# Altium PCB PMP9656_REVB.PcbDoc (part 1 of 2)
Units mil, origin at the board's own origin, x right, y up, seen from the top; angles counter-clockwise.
Board outline 5000 x 2000 mil, 4 copper layers (Top Layer, MidLayer1, MidLayer2, Bottom Layer), stack 60.2 mil thick; 89 components, 41 nets, 276 pads, 85 vias.
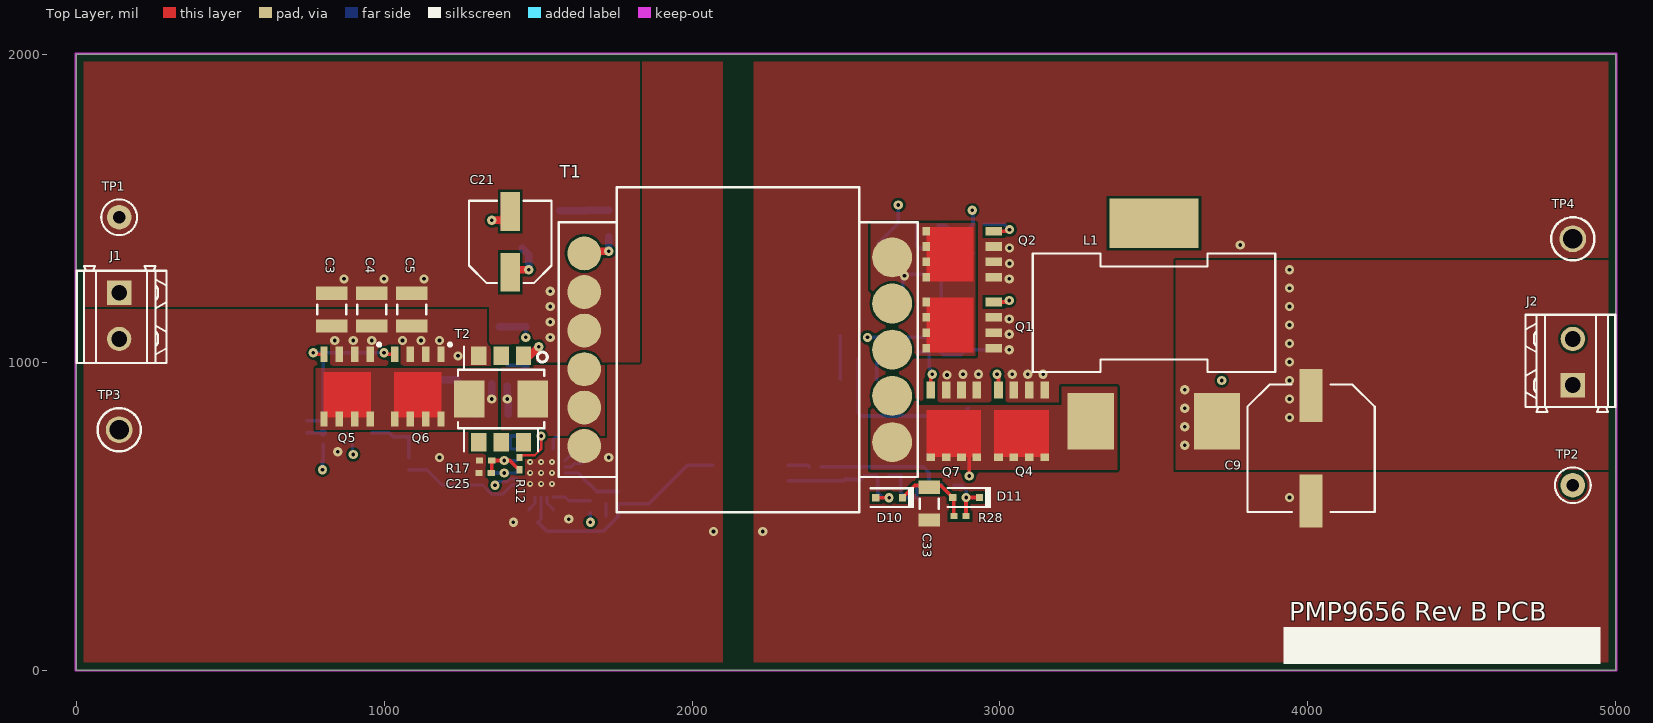
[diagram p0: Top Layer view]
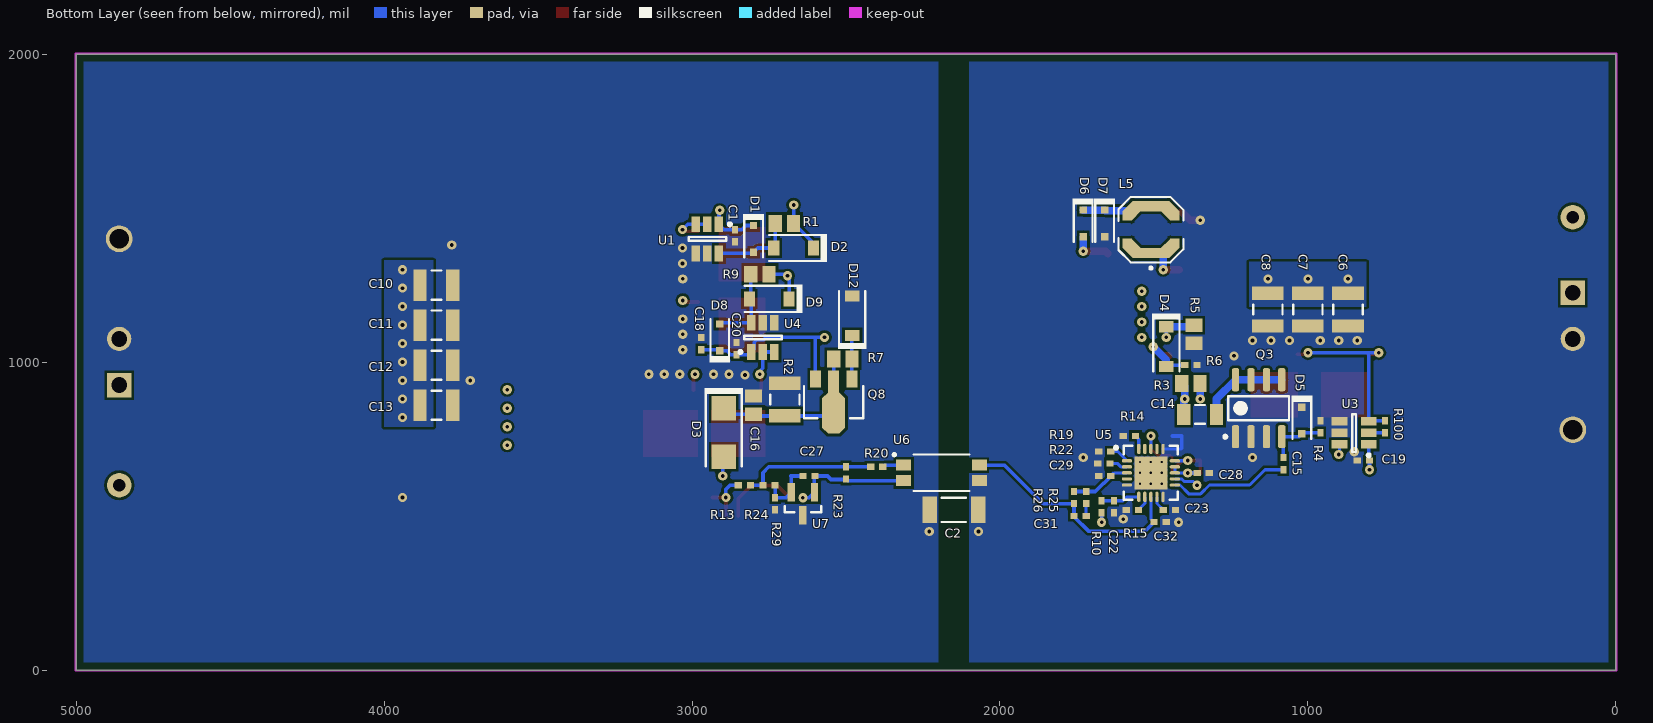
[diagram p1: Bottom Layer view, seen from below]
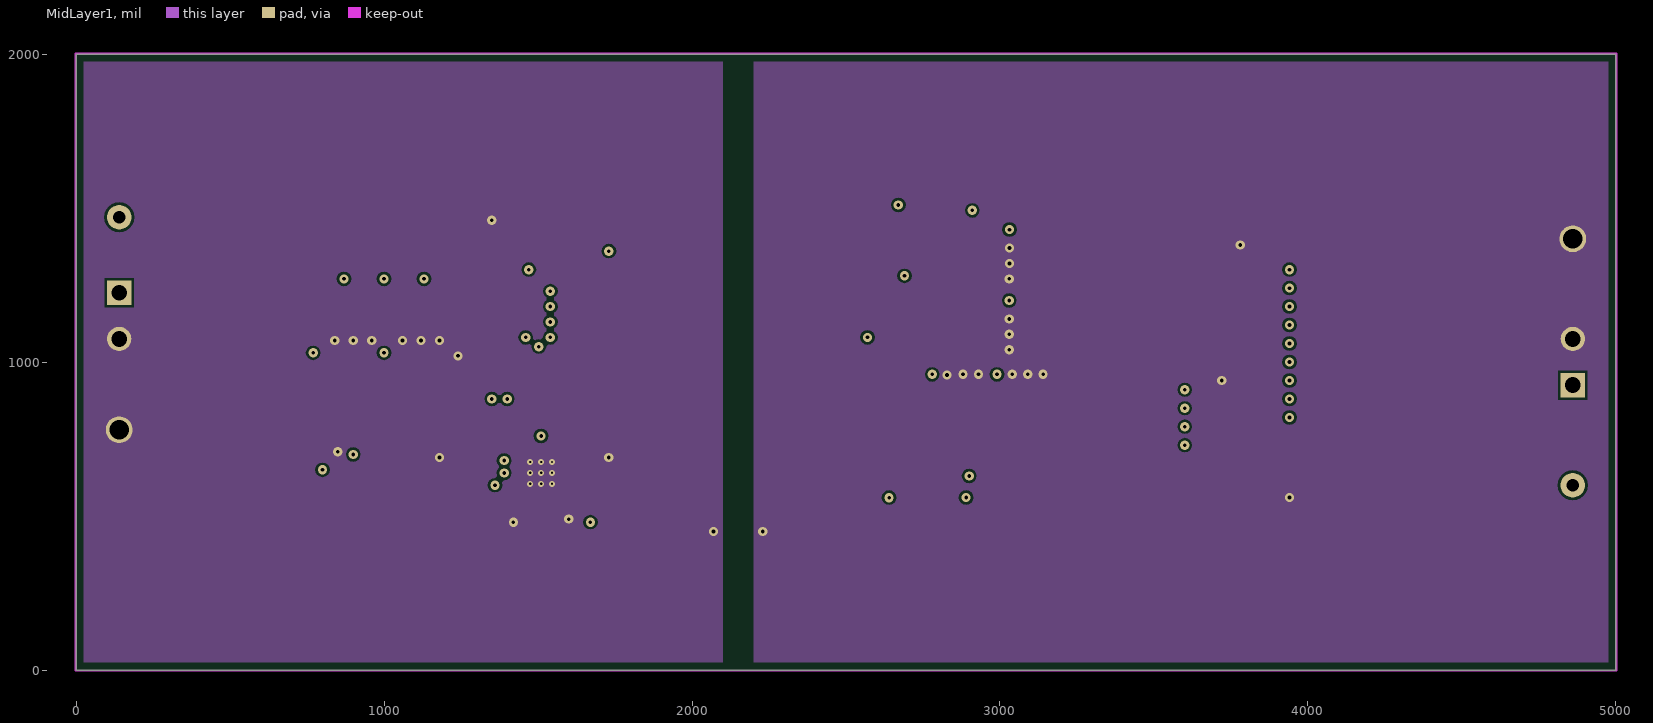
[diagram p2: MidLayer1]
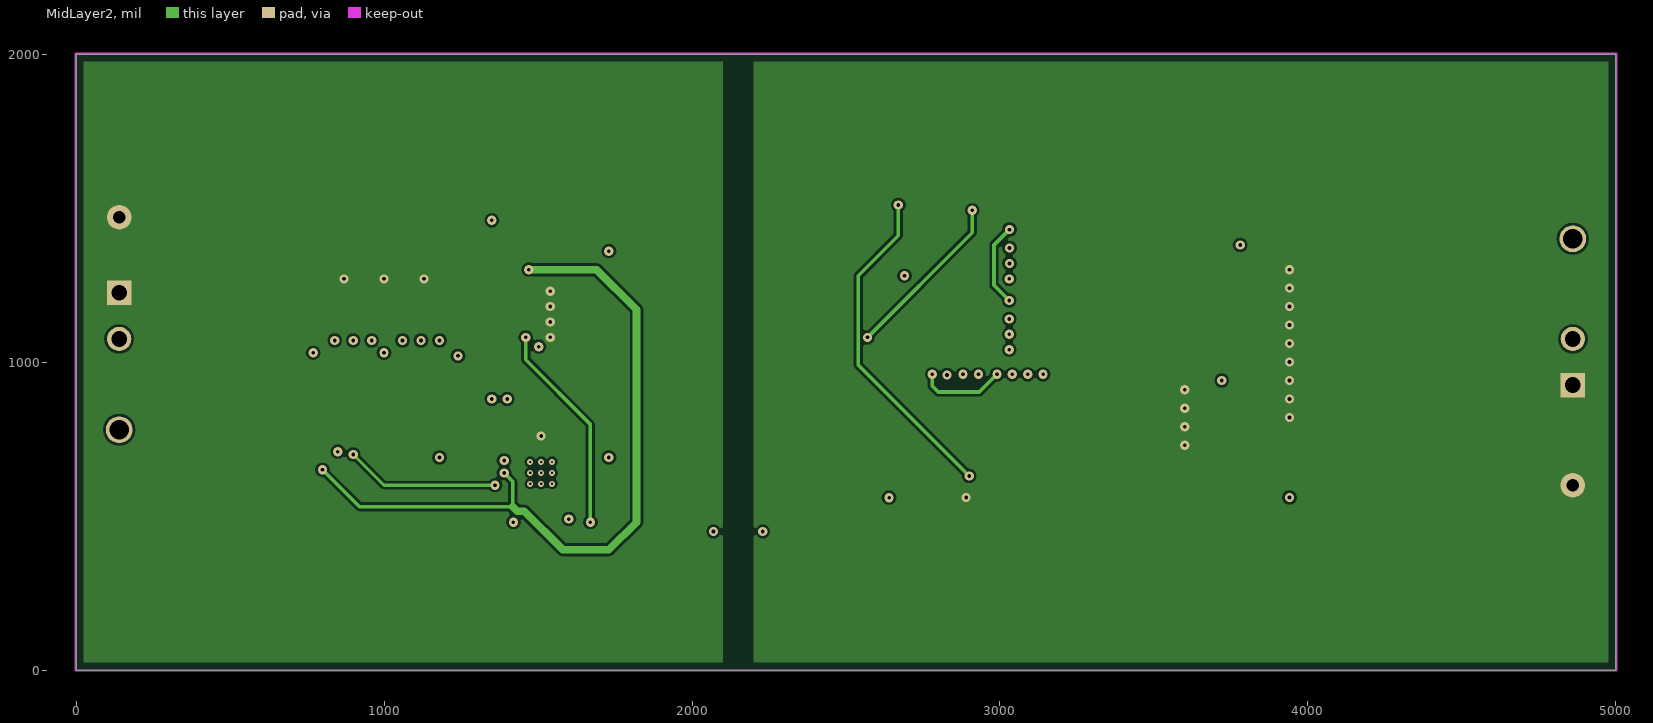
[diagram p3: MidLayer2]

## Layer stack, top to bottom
Top Solder: solder mask 0.4, Solder Resist, Dk 3.5
Top Layer: signal copper 1.4
Dielectric1: core 18.2, FR-4, Dk 4.8
MidLayer1: signal copper 1.4
Dielectric2: prepreg 18.2, FR-4, Dk 4.8
MidLayer2: signal copper 1.4
Dielectric3: core 18.2, FR-4, Dk 4.8
Bottom Layer: signal copper 1.4
Bottom Solder: solder mask 0.4, Solder Resist, Dk 3.5

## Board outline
0,0 5000,0 5000,2000 0,2000

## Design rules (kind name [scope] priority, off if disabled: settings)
AcuteAngle [All] p1: minimum=1.50000000000000E+0001 checktracksonly=TRUE
AssemblyTestPointUsage [All] p1: valid=2
Clearance Clearance_BoardEdge_MountingHoles [OnCopper and InComponentClass('Mounting Holes') vs IsKeepOut] p1: gap=25 ignorepadtopadclearanceinfootprint=FALSE except(0: Arc-Hole Track-Hole SMDPad-Hole THPad-Hole Via-Hole Fill-Hole Poly-Hole Region-Hole Text-Hole)
Clearance Clearance_BoardEdge_Poly [OnCopper and InPoly vs IsKeepOut] p2: gap=25 ignorepadtopadclearanceinfootprint=FALSE except(0: Arc-Hole Track-Hole SMDPad-Hole THPad-Hole Via-Hole Fill-Hole Poly-Hole Region-Hole Text-Hole)
Clearance Clearance_BoardEdge [OnCopper and Not InComponentClass('Logo') and not InComponentClass('FiducialMark') and not InRegion(1000,500,4000,800) and Not IsKeepout vs IsKeepOut] p3: gap=25 ignorepadtopadclearanceinfootprint=FALSE except(0: Arc-Hole Track-Hole SMDPad-Hole THPad-Hole Via-Hole Fill-Hole Poly-Hole Region-Hole Text-Hole)
Clearance Clearance_Poly [InPolygon] p4: gap=8 ignorepadtopadclearanceinfootprint=FALSE except(0: Arc-Hole Track-Hole SMDPad-Hole THPad-Hole Via-Hole Fill-Hole Poly-Hole Region-Hole Text-Hole)
Clearance [All] p5: gap=8 ignorepadtopadclearanceinfootprint=FALSE except(0: Arc-Hole Track-Hole SMDPad-Hole THPad-Hole Via-Hole Fill-Hole Poly-Hole Region-Hole Text-Hole)
ComponentClearance ComponentClearance_Shunt [InComponentClass('Header') vs InComponentClass('Shunt')] p1: gap=0 collisioncheckmode=3 verticalgap=0 showdistances=FALSE
ComponentClearance ComponentClearance_Logo [InComponentClass('Logo')] p2: gap=15 collisioncheckmode=3 verticalgap=10 showdistances=FALSE
ComponentClearance ComponentClearance_ScrewToNut [(HasFootprint('NY PMS 440 0025 PH')) vs (HasFootprint('Keystone_1902C'))] p3: gap=5 collisioncheckmode=3 verticalgap=10 showdistances=FALSE
ComponentClearance ComponentClearance_MountingHoles [InComponentClass('Mounting Holes')] p4: gap=15 collisioncheckmode=3 verticalgap=100000 showdistances=FALSE
ComponentClearance ComponentClearance_SmallPassives [HasFootprint('0201*') or HasFootprint('0402*') or HasFootprint('0508') or HasFootprint('0603*') or HasFootprint('0612') or HasFootprint('0805*') or HasFootprint('0815*') or HasFootprint('0830*') or HasFootprint('1206*') or HasFootprint('1210*') or HasFootprint('1808*') or HasFootprint('1812*') or HasFootprint('1825*') or HasFootprint('2010*') or HasFootprint('2220*') or HasFootprint('2225*') or HasFootprint('2512*') or HasFootprint('2728*') or HasFootprint('3518*') vs HasFootprint('0201*') or HasFootprint('0402*') or HasFootprint('0508') or HasFootprint('0603*') or HasFootprint('0612') or HasFootprint('0805*') or HasFootprint('0815*') or HasFootprint('0830*') or HasFootprint('1206*') or HasFootprint('1210*') or HasFootprint('1808*') or HasFootprint('1812*') or HasFootprint('1825*') or HasFootprint('2010*') or HasFootprint('2220*') or HasFootprint('2225*') or HasFootprint('2512*') or HasFootprint('2728*') or HasFootprint('3518*')] p5: gap=15 collisioncheckmode=3 verticalgap=10 showdistances=FALSE
ComponentClearance ComponentClearance_THtoSMT [IsThruComponent vs IsSMTComponent] p6: gap=15 collisioncheckmode=3 verticalgap=30 showdistances=FALSE
ComponentClearance ComponentClearance_THtoTH [IsThruComponent vs IsThruComponent] p7: gap=15 collisioncheckmode=3 verticalgap=30 showdistances=FALSE
ComponentClearance [All] p8: gap=15 collisioncheckmode=3 verticalgap=10 showdistances=FALSE
DiffPairsRouting [All] p1: maxlimit=100 minlimit=10 mostfreqgap=10 toplayer_minwidth=15 toplayer_maxwidth=15 toplayer_prefwidth=15 midlayer1_minwidth=15 midlayer1_maxwidth=15 midlayer1_prefwidth=15 midlayer2_minwidth=15 midlayer2_maxwidth=15 midlayer2_prefwidth=15 bottomlayer_minwidth=15 bottomlayer_maxwidth=15 bottomlayer_prefwidth=15 maxuncoupledlength=1000
FabricationTestPointUsage TestPointUsage [All] p1: valid=2 allowmultiple=FALSE
FabricationTestpoint Testpoint [All] p1: side=3 testpointundercomponent=TRUE minsize=40 maxsize=100 preferedsize=60 minholesize=0 maxholesize=40 preferedholesize=32 testpointgrid=1 allowsidetop=TRUE allowsidebottom=TRUE usegrid=TRUE gridtolerance=0.01
FanoutControl Fanout_LCC [IsLCC] p1: bgadir=Out bgaviamode=Centered fanoutstyle=Auto fanoutdirection=Alternating viagrid=1 // Fanout_LCC (Default Rule)
FanoutControl Fanout_BGA [IsBGA] p2: bgadir=Out bgaviamode=Centered fanoutstyle=Auto fanoutdirection=Alternating viagrid=1 // Fanout_BGA (Default Rule)
FanoutControl Fanout_Default [All] p4: bgadir=Out bgaviamode=Centered fanoutstyle=Auto fanoutdirection=Alternating viagrid=1 // Fanout_Default (Default Rule)
FanoutControl Fanout_Small [(CompPinCount < 5)] p5: bgadir=Out bgaviamode=Centered fanoutstyle=Auto fanoutdirection=OutThenIn viagrid=1 // Fanout_Small (Default Rule)
HoleSize [All] p1: absolutevalues=TRUE maxlimit=251 minlimit=7.8 maxpercent=80.000 minpercent=20.000
MinimumAnnularRing MinimumAnnularRing_ThermalPadVias [IsVia and InAnyComponent] p1: minimumring=5.91
MinimumAnnularRing [All] p2: minimumring=9
MinimumSolderMaskSliver MinimumSolderMaskSliver_Logo [InComponentClass('Logo') vs InComponentClass('Logo')] p1: minsoldermaskwidth=0.7
MinimumSolderMaskSliver [All] p2: minsoldermaskwidth=0
PlaneConnect [All] p1: planeconnectstyle=Relief reliefexpansion=10 reliefentries=4 reliefconductorwidth=10 reliefairgap=10
PolygonConnect [All] p1: connectstyle=Direct reliefconductorwidth=10 reliefentries=4 polygonreliefangle="90 Angle" airgapwidth=10
RoutingVias ThermalPadVias [IsVia and InAnyComponent] p1: holewidth=7.87 width=19.68 viastyle="Through Hole" minholewidth=7.87 minwidth=19.68 maxholewidth=12.99 maxwidth=23.62
RoutingVias [All] p2: holewidth=16 width=34 viastyle="Through Hole" minholewidth=7.87 minwidth=26 maxholewidth=40 maxwidth=65
SMDToCorner [All] p1: distance=0
SilkToSilkClearance [All] p1: silktosilkclearance=0
SilkToSolderMaskClearance SilkscreenOverComponentPads [IsPad] p1: minsilkscreentomaskgap=0 clearancetoexposedcopper=TRUE
SolderMaskExpansion [All] p1: expansion=1.97
Width [All] p1: maxlimit=100 minlimit=6 preferedwidth=10 checkconnectedcopper=TRUE
16 further rules are at their usual default settings.

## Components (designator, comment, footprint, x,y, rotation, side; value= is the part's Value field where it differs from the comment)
C1 "C1005X7R1H104M" 0402L 2860,1410 r270 bottom value=0.1uF
C2 "STD" 1808_L 2150,520 r180 bottom value=1000pF
C3 "GRM32ER72A225KA35L" 1210L 830,1170 r270 top value=2.2uF
C4 "GRM32ER72A225KA35L" 1210L 960,1170 r270 top value=2.2uF
C5 "GRM32ER72A225KA35L" 1210L 1090,1170 r270 top value=2.2uF
C6 "GRM32ER72A225KA35L" 1210L 870,1170 r270 bottom value=2.2uF
C7 "GRM32ER72A225KA35L" 1210L 1000,1170 r270 bottom value=2.2uF
C8 "GRM32ER72A225KA35L" 1210L 1130,1170 r270 bottom value=2.2uF
C9 "16SVP330M" SM_RADIAL_10AMM 4010,720 r270 top value=330uF
C10 "GRM32ER61E226KE15L" 1210L 3830,1250 r180 bottom value=22uF
C11 "GRM32ER61E226KE15L" 1210L 3830,1120 r180 bottom value=22uF
C12 "GRM32ER61E226KE15L" 1210L 3830,990 r180 bottom value=22uF
C13 "GRM32ER61E226KE15L" 1210L 3830,860 r180 bottom value=22uF
C14 "C3216X7R2E104K" 1206L 1350,830 r0 bottom value=0.1uF
C15 "C1005X7R1H104M" 0402L 1080,670 r90 bottom value=0.1uF
C16 "C2012X7R2A473K" 0805L 2800,860 r90 bottom value=0.047uF
C18 "GRM155R61H104ME14D" 0402L 2970,1060 r90 bottom value=0.1uF
C19 "C1005X7R1H104M" 0402L 820,680 r180 bottom value=0.1uF
C20 "C1005X7R1H104M" 0402L 2855.3,1043.54 r90 bottom value=0.1uF
C21 "EEE-FK1C221XP" SM_RADIAL_D8 1410,1390 r90 top value=220uF
C22 "CC0402KRX7R9BB101" 0402L 1630,530 r90 bottom value=100pF
C23 "GRM155R61A224KE19D" 0402L 1450,520 r0 bottom value=0.22uF
C25 "GRM155R71E473KA88D" 0402L 1328.19,640 r0 top value=0.047uF
C27 "C1005X7R1E103K" 0402L 2620,630 r0 bottom value=0.01uF
C28 "C1005X7R1H104M" 0402L 1340,640 r180 bottom value=0.1uF
C29 "GRM155R61A105KE15D" 0402L 1660,630 r0 bottom value=1uF
C31 "N/A" 0402L 1740,500 r180 bottom value=DNP
C32 "C1005X7R1H102K" 0402L 1480,480 r180 bottom value=1000pF
C33 "C3216X7R1E475K" 1206L 2770,540 r270 top value=4.7uF
D1 "BAS316,115" sod-323 2800,1400 r270 bottom value=100V
D2 "BAV21W-7-F" SOD-123 2670,1370 r0 bottom value=1.25V
D3 "US1B-13-F" SMA 2897.09,771.52 r270 bottom value=100V
D4 "BAV21W-7-F" SOD-123 1460,1050 r270 bottom value=1.25V
D5 "BAS316,115" sod-323 1020,810 r270 bottom value=1.4V
D6 "BAS316,115" sod-323 1730,1450 r270 bottom value=1.4V
D7 "BAS316,115" sod-323 1660,1450 r270 bottom value=1.4V
D8 "BAS316,115" sod-323 2910,1080 r90 bottom value=100V
D9 "BAV21W-7-F" SOD-123 2749.16,1205 r0 bottom value=1.25V
D10 "BAS316,115" sod-323 2640,559.68 r180 top value=1.4V
D11 "BAS316,115" sod-323 2890,560 r180 top value=1.4V
D12 "MMSZ4692-V" SOD-123 2480,1150 r90 bottom value=6.8V
J1 "691214310002" Wurth_691214310002 140,1150 r270 top
J2 "691214310002" Wurth_691214310002 4860,1000 r90 top
L1 "SER2014-402MLB" SER2014 3500,1160 r90 top value=4uH
L5 "LPS4414-105MLB" LPS4414 1510,1430 r90 bottom value=1mH
Q1 "CSD18532Q5B" TRANS_NexFET_Q5B 2870,1120 r180 top value=60V
Q2 "CSD18532Q5B" TRANS_NexFET_Q5B 2870,1350 r180 top value=60V
Q3 "IRF6216TRPBF" SO-8L 1160,850 r90 bottom value=-150V
Q4 "CSD18532Q5B" TRANS_NexFET_Q5B 3070,800 r270 top value=60V
Q5 "FDMS86200" TRANS_Fairchild_PQFN08A 880,920 r270 top value=150V
Q6 "FDMS86200" TRANS_Fairchild_PQFN08A 1110,920 r270 top value=150V
Q7 "CSD18532Q5B" TRANS_NexFET_Q5B 2850,800 r270 top value=60V
Q8 "BCX5616TA" SOT-89-3 2540,870 r270 bottom value=0.5V
R1 "CRCW08055K10JNEA" 0805L 2700,1450 r0 bottom value=5.1k
R2 "N/A" 1210L 2698.13,878.18 r270 bottom value=DNP
R3 "ERJ-6RSJR10V" 0805L 1380,930 r0 bottom value=0.1
R4 "CRCW040210K0FKED" 0402L 960,790 r270 bottom value=10.0k
R5 "RC0805FR-071R91L" 0805L 1370,1090 r90 bottom value=1.91
R6 "CRCW040210K0FKED" 0402L 1380,990 r0 bottom value=10.0k
R7 "CRCW080520K0FKEA" 0805L 2510,1010 r0 bottom value=20.0k
R9 "CRCW08055K10JNEA" 0805L 2779.32,1285 r0 bottom value=5.1k
R10 "CRCW04021K00FKED" 0402L 1670,530 r90 bottom value=1.00k
R12 "CRCW0402301KFKED" 0402L 1440,670 r90 top value=301k
R13 "CRCW04020000Z0ED" 0402L 2830,600 r180 bottom value=0
R14 "CRCW040213K0FKED" 0402L 1580,760 r180 bottom value=13.0k
R15 "CRCW0402100KFKED" 0402L 1570,520 r180 bottom value=100k
R17 "CRCW04028K66FKED" 0402L 1330,680 r0 top value=8.66k
R19 "CRCW040280K6FKED" 0402L 1660,710 r180 bottom value=80.6k
R20 "CRCW04022K00FKED" 0402L 2400,660 r0 bottom value=2.00k
R22 "CRCW0402124KFKED" 0402L 1662.84,671.05 r180 bottom value=124k
R23 "CRCW04024K99FKED" 0402L 2500,640 r90 bottom value=4.99k
R24 "CRCW040210K0FKED" 0402L 2750,600 r0 bottom value=10.0k
R25 "N/A" 0402L 1720,560 r270 bottom value=DNP
R26 "CRCW04021K00FKED" 0402L 1760,560 r270 bottom value=1.00k
R28 "CRCW040210K0FKED" 0402L 2870,500 r0 top value=10.0k
R29 "CRCW04022K61FKED" 0402L 2730,540 r90 bottom value=2.61k
R100 "CRCW04024R70JNED" 0402L 750,790 r90 bottom value=4.7
T1 "RA6992-BL" Coilcraft_RA6992-BL 2150,1040 r0 top value=50uH
T2 "CST2-100L" P82xx 1380,880 r270 top value=2000uH
TP1 "5000" Keystone5000 140,1470 r0 top value=Red
TP2 "5000" Keystone5000 4860,600 r0 top value=Red
TP3 "5011" Keystone5011 140,780 r0 top value=Black
TP4 "5011" Keystone5011 4860,1400 r0 top value=Black
U1 "UCC27511DBV" DBV0006A_M 2950,1400 r270 bottom
U3 "UCC27511DBV" DBV0006A_M 850,770 r0 bottom
U4 "UCC27511DBV" DBV0006A_M 2770,1080 r90 bottom
U5 "UCC2897ARGPR" RGP0020D 1510,640 r180 bottom
U6 "VOS617A-7X001T" SSOP-4_VISHAY 2190,640 r180 bottom
U7 "TL431AIDBZ" DBZ0003A_N 2640,540 r270 bottom

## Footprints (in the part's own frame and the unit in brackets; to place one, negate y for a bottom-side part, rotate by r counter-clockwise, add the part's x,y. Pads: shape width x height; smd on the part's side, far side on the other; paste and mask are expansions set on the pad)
0402L [mm] "0402 from SM-752 data"
  rect 0.6x0.5 smd: 1(-0.5,0) 2(0.5,0)
  body extent -0.55,-0.3 0.55,0.3, height 0.6
0805L [mm] "0805 from SM-752 data"
  rect 1.1x1.4 smd: 1(-0.75,0) 2(0.75,0)
  body extent -1.1,-0.72 1.1,0.72, height 1.1
1206L [mm] "1206 from SM-752 data"
  rect 1.1x1.75 smd: 1(-1.35,0) 2(1.35,0)
  silkscreen extent -0.4,-0.77 0.4,0.77, body extent -1.7,-0.9 1.7,0.9, height 1.35
1210L [mm] "1210 from SM-752 data"
  rect 1.1x2.6 smd: 1(-1.35,0) 2(1.35,0)
  silkscreen extent -0.4,-1.2 0.4,1.2, body extent -1.7,-1.35 1.7,1.35, height 1.35
1808_L [mm] "Chip Capacitor, Body 4.6x2.0mm, IPC High Density"
  rect 1.2x2.2 smd: 1(-2,0) 2(2,0)
  silkscreen extent -1,-1 1,1, body extent -2.47,-1.2 2.47,1.2, height 2.03
Coilcraft_RA6992-BL [mm] "COILCRAFT"
  round 2.79 smd: 1(-12.7,7.94) 2(-12.7,4.76) 3(-12.7,1.58) 4(-12.7,-1.6) 5(-12.7,-4.77) 6(-12.7,-7.94)
  round 3.3 smd: 7(12.7,-7.62) 8(12.7,-3.81) 9(12.7,0) 10(12.7,3.81) 11(12.7,7.62)
  silkscreen extent -14.8,-13.4 14.8,13.4, body extent -14.8,-13.33 14.8,13.33, height 12.11
DBV0006A_M [mm] "SOT23, 6-Leads, Body 2.9x1.6mm, Pitch 0.95mm, Lead Span 2.8mm, IPC Low Density"
  rect 1.3x0.7 smd: 1(-1.2,0.95) 2(-1.2,0) 3(-1.2,-0.95) 4(1.2,-0.95) 5(1.2,0) 6(1.2,0.95)
  silkscreen extent -1.32,-1.55 0.15,1.97, body extent -1.42,-1.46 1.42,1.46, height 1.11
DBZ0003A_N [mm] "SOT23, 3-Leads, Body 2.9x1.3mm, Pitch 0.95mm, Lead Span 2.4mm, IPC Medium Density"
  rect 1.5x0.6 smd: 1(-0.95,0.95) 2(-0.95,-0.95) 3(0.95,0)
  silkscreen extent 0.2,-1.5 0.7,1.5, body extent -1.26,-1.46 1.26,1.46, height 0.96
Keystone5000 [mil] "For Keystone 500x miniature loop terminals"
  round 80 hole 40: 1(0,0)
  silkscreen extent -58,-58 58,58, body extent -49,-49 49,49, height 182
Keystone5011 [mil] "Keystone Multipurpose loops"
  round 87 hole 63: 1(0,0)
  silkscreen extent -70,-70 70,70, body extent -63,-63 63,62, height 319
LPS4414 [mm] "Coilcraft recommended land pattern Document 548-2 10/1/10"
  rect 0.85x3 smd: 1(-1.925,0) 2(1.925,0)
  rect 1.202x1.07 smd rot 135: 1(-1.55,-1.55) 2(1.55,1.55)
  rect 1.202x1.07 smd rot 45: 1(-1.55,1.55) 2(1.55,-1.55)
  rect 0.75x0.775 smd: 1(-1.125,-1.963) 1(-1.125,1.963) 2(1.125,-1.963) 2(1.125,1.963)
  silkscreen extent -3.26,-2.68 2.7,2.68, body extent -2.2,-2.2 2.2,2.2, height 1.42
P82xx [mil] "Pulse recommended land pattern"
  rect 60x50 smd: 1(-140,73) 2(-140,0) 3(-140,-73) 4(140,-73) 5(140,0) 6(140,73)
  rect 120x100 smd: 7(0,-103) 8(0,103)
  silkscreen extent -170,-140 170,150, body extent -95,-140 95,140, height 215
RGP0020D [mm] "QFN, 20-Leads, Body 4x4mm, Pitch 0.5mm, Thermal Pad 2.7x2.7mm, TI Recommended"
  oval 0.85x0.28 smd paste-0.025 mask+0.07: 1(-1.975,1) 2(-1.975,0.5) 3(-1.975,0) 4(-1.975,-0.5) 5(-1.975,-1) 11(1.975,-1) 12(1.975,-0.5) 13(1.975,0) 14(1.975,0.5) 15(1.975,1)
  oval 0.28x0.85 smd paste-0.025 mask+0.07: 6(-1,-1.975) 7(-0.5,-1.975) 8(0,-1.975) 9(0.5,-1.975) 10(1,-1.975) 16(1,1.975) 17(0.5,1.975) 18(0,1.975) 19(-0.5,1.975) 20(-1,1.975)
  rect 2.7x2.7 smd paste-1.35 mask+0.07: 21(0,0)
  silkscreen extent -3,-2.22 2.22,2.22, body extent -2.07,-2.07 2.07,2.07, height 1
SER2014 [mil] "Coilcraft recommended land pattern.  Document 349-1, rev 02/24/10"
  rect 185x150 smd: 1(-352.25,205) 2(-352.25,-205)
  rect 160x290 smd: 3(290.25,0)
  silkscreen extent -193,-394 193,394, body extent -412,-390 324,390, height 550
SM_RADIAL_10AMM [mm] "10 x 7.9mm:  Sanyo Oscon F8"
  rect 4.4x1.9 smd: 1(-4.35,0) 2(4.35,0)
  silkscreen extent -5.25,-5.25 5.25,5.25, body extent -5.25,-5.25 5.25,5.25, height 8
SM_RADIAL_D8 [mm] "6.3 x 7.7mm:  Panasonic D8"
  rect 3.2x1.6 smd: 1(-2.5,0) 2(2.5,0)
  silkscreen extent -3.4,-3.4 3.4,3.4, body extent -3.4,-3.4 3.4,3.4, height 8.01
SMA [mm] "Molded Diode, 2-Leads, Body 4.3x2.6mm, IPC Medium Density, based on OnSemi component dimensions and land pattern"
  rect 2x2 smd: 1(-2,0) 2(2,0)
  silkscreen extent -3.66,-1.57 2.79,1.57, body extent -2.6,-1.3 2.6,1.3, height 2.42
SO-8L [mm] "SOIC, 8-Leads, Body 5.0x4.0mm (max), Pitch 1.27mm, IPC Most Density"
  rrect50% 1.9x0.6 smd: 1(-2.35,1.905) 2(-2.35,0.635) 3(-2.35,-0.635) 4(-2.35,-1.905) 5(2.35,-1.905) 6(2.35,-0.635) 7(2.35,0.635) 8(2.35,1.905)
  silkscreen extent -2.47,-2.5 1,2.88, body extent -3,-2.45 3,2.45, height 1.59
SOD-123 [mm] "On Semi recommended land pattern"
  rect 0.915x1.22 smd: 1(-1.637,0) 2(1.637,0)
  silkscreen extent -2.74,-1.17 2.03,1.17, body extent -1.93,-0.9 1.93,0.9, height 1.35
sod-323 [mm] "NXP recommended land pattern"
  rect 0.6x0.6 smd paste-0.05: 1(-1.1,0) 2(1.1,0)
  silkscreen extent -2.06,-0.86 1.53,0.86, body extent -1.3,-0.67 1.3,0.68, height 1.1
SOT-89-3 [mm] "SOT, 3-Leads, Body 4.6 x 2.6 mm, Pitch 1.5mm"
  rect 1.4x0.9 smd: 1(-1.9,1.5) 3(-1.9,-1.5)
  rect 1.8x0.9 smd: 2(-1.7,0)
  oct 3.4x1.9 smd: 4(0.9,0)
  silkscreen extent -1.3,-2.45 1.33,2.45, body extent -2.42,-2.28 1.83,2.32, height 1.62
SSOP-4_VISHAY [mm] "Vishay Recommened"
  rect 1.25x0.9 smd: 1(-3.125,0.635) 2(-3.125,-0.635) 3(3.125,-0.635) 4(3.125,0.635)
  silkscreen extent -3.98,-1.5 2.3,1.59, body extent -3.5,-1.45 3.5,1.45, height 2.42
TRANS_Fairchild_PQFN08A [mm] "Fairchild PQFN08A recommended land pattern"
  rect 1.27x0.61 smd: 1(-2.67,1.905) 2(-2.67,0.635) 3(-2.67,-0.635) 4(-2.67,-1.905) 5(2.67,-1.905) 6(2.67,-0.635) 7(2.67,0.635) 8(2.67,1.905)
  Top Layer region: 2.535,-1.955 2.535,1.955 -1.215,1.955 -1.215,-1.955
  silkscreen extent -3.6,2.52 -3.34,2.77, body extent -3.05,-2.55 3.05,2.55, height 1.11
TRANS_NexFET_Q5B [mm] "TI recommended land pattern (nominal) November 2012"
  rect 1.372x0.71 smd paste-0.4 mask+0.051: 1(-2.776,1.905) 2(-2.776,0.635) 3(-2.776,-0.635) 4(-2.776,-1.905)
  rect 0.59x0.71 smd paste-0.3: 5(2.776,-1.905) 6(2.776,-0.635) 7(2.776,0.635) 8(2.776,1.905)
  Top Layer region: -1.106,-2.26 2.744,-2.26 2.744,2.26 -1.106,2.26
  body extent -3.23,-2.55 2.87,2.55, height 1.06
Wurth_691214310002 [mm] "WE"
  rect 2x2 hole 1.3: 1(-1.905,0)
  round 2 hole 1.3: 2(1.905,0)
  silkscreen extent -4.12,-3.5 3.9,3.9, body extent -4.12,-3.5 3.9,3.9, height 8.52

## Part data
C1 C15 C19 C20 C28: "CAP, CERM, 0.1uF, 50V, +/-20%, C0G/NP0, 0402", Cap_Case=0402, Manufacturer=TDK, Supplier Part Number 1=445-5933-1-ND, TempCo=C0G/NP0, Tolerance_%=20, Value1=Unknown, Value2=50V, ValueDisplayed=0.1µF
C2: library part VJ1808Y102KXEAT5Z, "CAP, CERM, 1000pF, 3kV, 1808", Cap_Case=1808, TempCo=X7R, Tolerance_%=10, Value1=Unknown, Value2=3kV, ValueDisplayed=1000pF
C3 C4 C5 C6 C7 C8: "CAP, CERM, 2.2uF, 100V, +/-10%, X7R, 1210", Cap_Case=1210, Manufacturer=MuRata, Supplier Part Number 1=490-3385-1-ND, TempCo=X7R, Tolerance_%=10, Value1="0.007 ohm", Value2=100V, ValueDisplayed=2.2µF
C9: "CAP, OS-CON, 330uF, 16V, +/-20%, 0.016 ohm, 10x10.3 SMD", Cap_Case=10.3x10.3x12.6, Manufacturer=Sanyo, Supplier Part Number 1=9189084, Tolerance_%=20, Value1="0.016 ohm", Value2=16V, ValueDisplayed=330µF
C10 C11 C12 C13: "CAP, CERM, 22uF, 25V, +/-10%, X5R, 1210", Cap_Case=1210, Manufacturer=MuRata, Supplier Part Number 1=81-GRM32ER61E226KE15, TempCo=X5R, Tolerance_%=10, Value1="0.002 ohm", Value2=25V, ValueDisplayed=22µF
C14: "CAP, CERM, 0.1uF, 250V, +/-10%, X7R, 1206", Cap_Case=1206, Manufacturer=TDK, Supplier Part Number 1=445-2287-1-ND, TempCo=X7R, Tolerance_%=10, Value1="0.0217 ohm", Value2=250V, ValueDisplayed=0.1µF
C16: "CAP, CERM, 0.047uF, 100V, +/-10%, X7R, 0805", Cap_Case=0805, Manufacturer=TDK, Supplier Part Number 1=445-2276-1-ND, TempCo=X7R, Tolerance_%=10, Value1="0.0211 ohm", Value2=100V, ValueDisplayed=0.047µF
C18: "CAP, CERM, 0.1 µF, 50 V,+/- 20%, X5R, 0402", Cap_Case=0402, Manufacturer=MuRata, Supplier Part Number 1=GRM155R61H104ME14D-ND, TempCo=X5R, Tolerance_%=20, Value2=50V, ValueDisplayed=0.1µF
C21: "CAP, AL, 220uF, 16V, +/-20%, 0.34 ohm, SMD", Cap_Case=D8, Manufacturer=Panasonic, Supplier Part Number 1=PCE3788CT-ND, Tolerance_%=20, Value1="0.34 ohm", Value2=16V, ValueDisplayed=220µF
C22: "CAP, CERM, 100pF, 50V, +/-10%, X7R, 0402", Cap_Case=0402, Manufacturer="Yageo America", Supplier Part Number 1=311-1419-1-ND, TempCo=X7R, Tolerance_%=10, Value1=Unknown, Value2=50V, ValueDisplayed=100pF
C23: "CAP, CERM, 0.22uF, 10V, +/-10%, X5R, 0402", Cap_Case=0402, Manufacturer=MuRata, Supplier Part Number 1=490-3910-1-ND, TempCo=X5R, Tolerance_%=10, Value1=Unknown, Value2=10V, ValueDisplayed=0.22µF
C25: "CAP, CERM, 0.047uF, 25V, +/-10%, X7R, 0402", Cap_Case=0402, Manufacturer=MuRata, Supplier Part Number 1=490-3254-1-ND, TempCo=X7R, Tolerance_%=10, Value1=Unknown, Value2=25V, ValueDisplayed=0.047µF
C27: "CAP, CERM, 0.01uF, 25V, +/-10%, X7R, 0402", Cap_Case=0402, Manufacturer=TDK, Supplier Part Number 1=445-1260-1-ND, TempCo=X7R, Tolerance_%=10, Value1="0.0623 ohm", Value2=25V, ValueDisplayed=0.01µF
C29: "CAP, CERM, 1uF, 10V, +/-10%, X5R, 0402", Cap_Case=0402, Manufacturer=MuRata, Supplier Part Number 1=490-3890-1-ND, TempCo=X5R, Tolerance_%=10, Value1=Unknown, Value2=10V, ValueDisplayed=1µF
C31: library part 04025C132KAT2A, "Do Not Populate", Cap_Case=0402, TempCo=X7R, Tolerance_%=10, Value1=Unknown, Value2=50V, ValueDisplayed=1300pF
C32: "CAP, CERM, 1000pF, 50V, +/-10%, X7R, 0402", Cap_Case=0402, Manufacturer=TDK, Supplier Part Number 1=445-1256-1-ND, TempCo=X7R, Tolerance_%=10, Value1="0.2381 ohm", Value2=50V, ValueDisplayed=1000pF
C33: "CAP, CERM, 4.7uF, 25V, +/-10%, X7R, 1206", Cap_Case=1206, Manufacturer=TDK, Supplier Part Number 1=445-1606-1-ND, TempCo=X7R, Tolerance_%=10, Value1="0.0063 ohm", Value2=25V, ValueDisplayed=4.7µF
D1 D8: "Diode, Ultrafast, 100V, 0.25A, SOD-323", Manufacturer="NXP Semiconductor", Supplier Part Number 1=568-5003-1-ND, Value1=0.25A, Value2=1.4V
D2 D4 D9: "Diode, Switching, 200V, 0.2A, SOD-123", Manufacturer="Diodes Inc.", Supplier Part Number 1=BAV21W-FDICT-ND, Value1=0.2A, Value2=200V
D3: "Diode, Ultrafast, 100V, 1A, SMA", Manufacturer="Diodes Inc.", Supplier Part Number 1=US1B-FDICT-ND, Value1=1A, Value2=1V
D5 D6 D7 D10 D11: "Diode, Ultrafast, 100V, 0.25A, SOD-323", Manufacturer="NXP Semiconductor", Supplier Part Number 1=568-5003-1-ND, Value1=0.25A, Value2=100V
D12: "Diode, Zener, 6.8V, 500mW, SOD-123", Manufacturer=Vishay-Semiconductor, Power_W=0.5, Supplier Part Number 1=69R4763, Value1=0.5W
J1 J2: "Terminal Block, 2x1, 3.81mm, 24-16 AWG, 10A, 300VAC, TH", Manufacturer="Wurth Elektronik eiSos"
L1: "Inductor, Shielded E Core, Ferrite, 4uH, 25A, 0.00194 ohm, SMD", Manufacturer=Coilcraft, Value1="0.00194 ohm", Value2=25A, ValueDisplayed=4µH
L5: "Inductor, Shielded Drum Core, Ferrite, 1mH, 0.11A, 16.3 ohm, SMD", Manufacturer=Coilcraft, Value1="16.3 ohm", Value2=0.11A, ValueDisplayed=1mH
Q1 Q2 Q4 Q7: "MOSFET, N-CH, 60V, 172A, SON 5x6mm", Alternate Manufacturer=None, Manufacturer="Texas Instruments", Supplier Part Number 1=296-35628-1-ND, Value1="3.3 ohm", Value2="27 nC"
Q3: "MOSFET, P-CH, -150V, -2.2A, SO-8", Alternate Manufacturer=None, Manufacturer="International Rectifier", Supplier Part Number 1=IRF6216TRPBFCT-ND, Value1="? ohm", Value2="15 nC"
Q5 Q6: "MOSFET, N-CH, 150V, 35A, PQFN08A", Alternate Manufacturer=None, Manufacturer="Fairchild Semiconductor", Supplier Part Number 1=FDMS86200CT-ND, Value1="101 ohm", Value2="33 nC"
Q8: library part "BCX5616TA, Diodes Inc.", "Transistor, NPN, 80V, 1A, SOT-89", Manufacturer="Diodes Inc.", Supplier Part Number 1=BCX5616CT-ND, Value1=1A, Value2=250
R1 R9: "RES, 5.1k ohm, 5%, 0.125W, 0805", Manufacturer=Vishay-Dale, Power_W=0.125, Supplier Part Number 1=541-5.1KACT-ND, TempCo="200 ppm/C", Tolerance_%=5, Value1=5%, Value2=0.125W, Value_Code=5k10
R2: library part ERJ-L14KF10CU, "Do Not Populate", Power_W=0.33, TempCo="100 ppm/C", Tolerance_%=1, Value1=1%, Value2=0.33W, Value_Code=R100
R3: "RES, 0.1 ohm, 5%, 0.125W, 0805", Manufacturer=Panasonic, Power_W=0.125, Supplier Part Number 1=P.10BCT-ND, TempCo="250 ppm/C", Tolerance_%=5, Value1=5%, Value2=0.125W, Value_Code=R100
R4 R6 R24 R28: "RES, 10.0k ohm, 1%, 0.063W, 0402", Manufacturer=Vishay-Dale, Power_W=0.063, Supplier Part Number 1=541-10.0KLCT-ND, TempCo="100 ppm/C", Tolerance_%=1, Value1=1%, Value2=0.063W, Value_Code=10k0
R5: "RES, 1.91 ohm, 1%, 0.125W, 0805", Manufacturer="Yageo America", Power_W=0.125, Supplier Part Number 1=311-1.91CRCT-ND, TempCo="200 ppm/C", Tolerance_%=1, Value1=1%, Value2=0.125W, Value_Code=1R91
R7: "RES, 20.0k ohm, 1%, 0.125W, 0805", Manufacturer=Vishay-Dale, Power_W=0.125, Supplier Part Number 1=541-20.0KCCT-ND, TempCo="100 ppm/C", Tolerance_%=1, Value1=1%, Value2=0.125W, Value_Code=20k0
R10 R26: "RES, 1.00k ohm, 1%, 0.063W, 0402", Manufacturer=Vishay-Dale, Power_W=0.063, Supplier Part Number 1=541-1.00KLCT-ND, TempCo="100 ppm/C", Tolerance_%=1, Value1=1%, Value2=0.063W, Value_Code=1k00
R12: "RES, 301k ohm, 1%, 0.063W, 0402", Manufacturer=Vishay-Dale, Power_W=0.063, Supplier Part Number 1=541-301KLCT-ND, TempCo="100 ppm/C", Tolerance_%=1, Value1=1%, Value2=0.063W, Value_Code=301k
R13: "RES, 0 ohm, 5%, 0.063W, 0402", Manufacturer=Vishay-Dale, Power_W=0.063, Supplier Part Number 1=541-0.0JCT-ND, TempCo="200 ppm/C", Tolerance_%=5, Value1=5%, Value2=0.063W, Value_Code=0000
R14: "RES, 13.0k ohm, 1%, 0.063W, 0402", Manufacturer=Vishay-Dale, Power_W=0.063, Supplier Part Number 1=541-13.0KLCT-ND, TempCo="100 ppm/C", Tolerance_%=1, Value1=1%, Value2=0.063W, Value_Code=13k0
R15: "RES, 100k ohm, 1%, 0.063W, 0402", Manufacturer=Vishay-Dale, Power_W=0.063, Supplier Part Number 1=541-100KLCT-ND, TempCo="100 ppm/C", Tolerance_%=1, Value1=1%, Value2=0.063W, Value_Code=100k
R17: "RES, 8.66k ohm, 1%, 0.063W, 0402", Manufacturer=Vishay-Dale, Power_W=0.063, Supplier Part Number 1=541-8.66KLCT-ND, TempCo="100 ppm/C", Tolerance_%=1, Value1=1%, Value2=0.063W, Value_Code=8k66
R19: "RES, 80.6k ohm, 1%, 0.063W, 0402", Manufacturer=Vishay-Dale, Power_W=0.063, Supplier Part Number 1=541-80.6KLCT-ND, TempCo="100 ppm/C", Tolerance_%=1, Value1=1%, Value2=0.063W, Value_Code=80k6
R20: "RES, 2.00k ohm, 1%, 0.063W, 0402", Manufacturer=Vishay-Dale, Power_W=0.063, Supplier Part Number 1=541-2.00KLCT-ND, TempCo="100 ppm/C", Tolerance_%=1, Value1=1%, Value2=0.063W, Value_Code=2k00
R22: "RES, 124k ohm, 1%, 0.063W, 0402", Manufacturer=Vishay-Dale, Power_W=0.063, Supplier Part Number 1=541-124KLCT-ND, TempCo="100 ppm/C", Tolerance_%=1, Value1=1%, Value2=0.063W, Value_Code=124k
R23: "RES, 4.99k ohm, 1%, 0.063W, 0402", Manufacturer=Vishay-Dale, Power_W=0.063, Supplier Part Number 1=541-4.99KLCT-ND, TempCo="100 ppm/C", Tolerance_%=1, Value1=1%, Value2=0.063W, Value_Code=4k99
R25: library part CRCW0402133RFKED, "Do Not Populate", Power_W=0.063, TempCo="100 ppm/C", Tolerance_%=1, Value1=1%, Value2=0.063W, Value_Code=133R
R29: "RES, 2.61k ohm, 1%, 0.063W, 0402", Manufacturer=Vishay-Dale, Power_W=0.063, Supplier Part Number 1=541-2.61KLCT-ND, TempCo="100 ppm/C", Tolerance_%=1, Value1=1%, Value2=0.063W, Value_Code=2k61
R100: "RES, 4.7 ohm, 5%, 0.063W, 0402", Manufacturer=Vishay-Dale, Power_W=0.063, Supplier Part Number 1=541-4.7JCT-ND, TempCo="200 ppm/C", Tolerance_%=5, Value1=5%, Value2=0.063W, Value_Code=4R70
T1: "Transformer, 50uH, SMT", Manufacturer=Coilcraft
T2: "Transformer, 2000uH, SMT", Manufacturer=Coilcraft
TP1 TP2: "Test Point, Miniature, Red, TH", Manufacturer=Keystone, Supplier Part Number 1=5000K-ND
TP3 TP4: "Test Point, Multipurpose, Black, TH", Manufacturer=Keystone, Supplier Part Number 1=5011K-ND
U1 U3 U4: "Single-Channel High-Speed Low-Side Gate Driver (with 4-A Peak Source and 8-A Peak Sink), DBV0006A", Alternate Manufacturer=None, Manufacturer="Texas Instruments"
U5: "Advanced Active Clamp PWM Controller with Current Control, -40 to +125 degC, 20-pin QFN (RGP), Green (RoHS & no Sb/Br)", Alternate Manufacturer=None, Alternate PartNumber=Equivalent, Frequency(Max)(kHz)=1000, Manufacturer="Texas Instruments", Rating=Catalog, Supplier Part Number 1=UCC2897ARGPR-ND
U6: "OptoCoupler, Phototransitor, 80-160%, SSOP-4", Manufacturer=Vishay-Semiconductor, Supplier Part Number 1=VOS617A-7X001T-ND
U7: "PRECISION PROGRAMMABLE REFERENCE, DBZ0003A", Alternate Manufacturer=None, Manufacturer="Texas Instruments"

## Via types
v1: diameter 30, hole 12, Top Layer to Bottom Layer, 76 vias
v2: diameter 19.68, hole 7.87, Top Layer to Bottom Layer, 9 vias

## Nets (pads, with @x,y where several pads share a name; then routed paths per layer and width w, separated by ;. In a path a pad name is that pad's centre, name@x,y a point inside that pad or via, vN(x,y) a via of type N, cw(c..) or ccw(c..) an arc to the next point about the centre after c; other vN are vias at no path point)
BIAS: C19.2 C21.1 C28.1 L5.1 U3.1 U5.13 U5.14 | length 2685.8
  Top Layer w25: C21.1@1418.43,1300 v1(1470,1300)
  MidLayer2 w12: v1(800,650) 920,530 1418.35,530 1418.35,611.65 v1(1390,640)
  MidLayer2 w25: 1418.35,530 1432.85,515.5 1455.5,515.5 1581,390 1730,390 1820,480 1820,1170 1690,1300 v1(1470,1300)
  Bottom Layer w10: v1(1390,640) U5.13@1432.24,640 U5.14@1432.24,659.68
  Bottom Layer w12: v1(800,650) 800,679.69 C19.2@800.31,680 802.76,682.44 U3.1@802.76,732.6 ; C28.1@1359.69,640 v1(1390,640)
  Bottom Layer w25: L5.1@1448.98,1368.98 1470,1347.95 v1(1470,1300)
